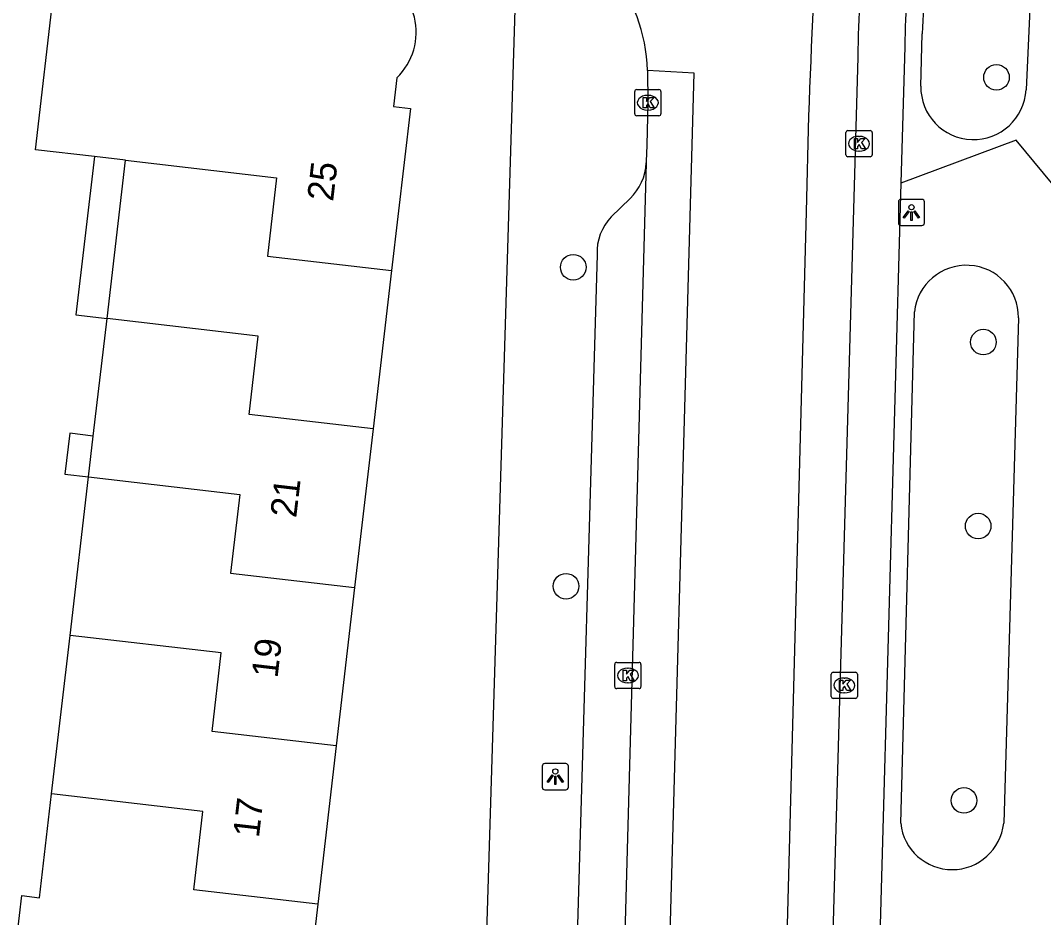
# Model space of a CAD drawing. Extents: x 162082 to 163393, y 388091 to 388632.
# Drawn here: x 162880.67 to 162919.73, y 388158.33 to 388192.57 of the extents above; entities that cross this region are included whole.
import ezdxf

# ---------------------------------------------------------------- set-up
doc = ezdxf.new("R2010")
doc.units = 0
for name, color, linetype in [('IMGEO_Boom', 7, 'Continuous'), ('IMGEO_Kolk', 7, 'Continuous'), ('IMGEO_Lichtpunt', 7, 'Continuous'), ('IMGEO_Pand', 7, 'Continuous'), ('IMGEO_Pand_nummerreeks', 7, 'Continuous'), ('IMGEO_Pand_overbouw', 7, 'Continuous'), ('IMGEO_Rijbaan_lokaal_gesloten', 7, 'Continuous'), ('IMGEO_Voetpad_open', 7, 'Continuous')]:
    doc.layers.add(name, color=color, linetype=linetype)

msp = doc.modelspace()

# ---------------------------------------------------------------- linework, layer by layer
at = {"layer": 'IMGEO_Boom'}
for centre in [(162917.93, 388190.397), (162901.772, 388183.148), (162917.431, 388180.294), (162917.231, 388173.271), (162901.498, 388170.974), (162916.689, 388162.799)]:
    msp.add_circle(centre, 0.489, dxfattribs=at)
at = {"layer": 'IMGEO_Kolk'}
for p, q in [((162904.119, 388189.004), (162904.119, 388189.856)), ((162904.194, 388189.93), (162905.046, 388189.93)), ((162905.12, 388189.856), (162905.12, 388189.004)), ((162904.607, 388189.71), (162904.632, 388189.71)), ((162904.63, 388189.15), (162904.605, 388189.15)), ((162905.046, 388188.93), (162904.194, 388188.93)), ((162912.183, 388187.44), (162912.183, 388188.292)), ((162912.258, 388188.366), (162913.11, 388188.366)), ((162913.184, 388188.292), (162913.184, 388187.44)), ((162912.671, 388188.146), (162912.696, 388188.146)), ((162912.694, 388187.586), (162912.669, 388187.586)), ((162913.11, 388187.366), (162912.258, 388187.366)), ((162903.356, 388167.141), (162903.356, 388167.993)), ((162903.431, 388168.067), (162904.283, 388168.067)), ((162904.357, 388167.993), (162904.357, 388167.141)), ((162903.844, 388167.847), (162903.869, 388167.847)), ((162911.622, 388166.765), (162911.622, 388167.617)), ((162911.697, 388167.691), (162912.549, 388167.691)), ((162912.623, 388167.617), (162912.623, 388166.765)), ((162903.867, 388167.287), (162903.842, 388167.287)), ((162912.11, 388167.471), (162912.135, 388167.471)), ((162904.283, 388167.067), (162903.431, 388167.067)), ((162912.133, 388166.911), (162912.108, 388166.911)), ((162912.549, 388166.691), (162911.697, 388166.691))]:
    msp.add_line(p, q, dxfattribs=at)
for points in [[(162904.119, 388189.004), (162904.119, 388189.856)], [(162904.194, 388189.93), (162905.046, 388189.93)], [(162905.12, 388189.856), (162905.12, 388189.004)], [(162904.44, 388189.63), (162904.563, 388189.63), (162904.563, 388189.479), (162904.693, 388189.63), (162904.857, 388189.63), (162904.711, 388189.479), (162904.864, 388189.23), (162904.712, 388189.23), (162904.627, 388189.394), (162904.563, 388189.327), (162904.563, 388189.23), (162904.44, 388189.23), (162904.44, 388189.63)], [(162905.046, 388188.93), (162904.194, 388188.93)], [(162912.183, 388187.44), (162912.183, 388188.292)], [(162912.258, 388188.366), (162913.11, 388188.366)], [(162913.184, 388188.292), (162913.184, 388187.44)], [(162912.504, 388188.066), (162912.627, 388188.066), (162912.627, 388187.915), (162912.757, 388188.066), (162912.921, 388188.066), (162912.775, 388187.915), (162912.928, 388187.666), (162912.776, 388187.666), (162912.691, 388187.83), (162912.627, 388187.763), (162912.627, 388187.666), (162912.504, 388187.666), (162912.504, 388188.066)], [(162913.11, 388187.366), (162912.258, 388187.366)], [(162903.356, 388167.141), (162903.356, 388167.993)], [(162903.431, 388168.067), (162904.283, 388168.067)], [(162904.357, 388167.993), (162904.357, 388167.141)], [(162903.677, 388167.767), (162903.8, 388167.767), (162903.8, 388167.616), (162903.93, 388167.767), (162904.094, 388167.767), (162903.948, 388167.616), (162904.101, 388167.367), (162903.949, 388167.367), (162903.864, 388167.531), (162903.8, 388167.464), (162903.8, 388167.367), (162903.677, 388167.367), (162903.677, 388167.767)], [(162911.622, 388166.765), (162911.622, 388167.617)], [(162911.697, 388167.691), (162912.549, 388167.691)], [(162912.623, 388167.617), (162912.623, 388166.765)], [(162911.943, 388167.391), (162912.066, 388167.391), (162912.066, 388167.24), (162912.196, 388167.391), (162912.36, 388167.391), (162912.214, 388167.24), (162912.367, 388166.991), (162912.215, 388166.991), (162912.13, 388167.155), (162912.066, 388167.088), (162912.066, 388166.991), (162911.943, 388166.991), (162911.943, 388167.391)], [(162904.283, 388167.067), (162903.431, 388167.067)], [(162912.549, 388166.691), (162911.697, 388166.691)]]:
    msp.add_lwpolyline(points, dxfattribs=at)
for centre, start, end in [((162904.196, 388189.854), 91.552, 178.448), ((162904.196, 388189.854), 91.552, 178.448), ((162905.044, 388189.854), 1.552, 88.448), ((162905.044, 388189.854), 1.552, 88.448), ((162904.196, 388189.006), 181.552, 268.448), ((162904.196, 388189.006), 181.552, 268.448), ((162905.044, 388189.006), 271.552, 358.448), ((162905.044, 388189.006), 271.552, 358.448), ((162912.26, 388188.29), 91.552, 178.448), ((162912.26, 388188.29), 91.552, 178.448), ((162913.108, 388188.29), 1.552, 88.448), ((162913.108, 388188.29), 1.552, 88.448), ((162912.26, 388187.442), 181.552, 268.448), ((162912.26, 388187.442), 181.552, 268.448), ((162913.108, 388187.442), 271.552, 358.448), ((162913.108, 388187.442), 271.552, 358.448), ((162903.433, 388167.991), 91.552, 178.448), ((162903.433, 388167.991), 91.552, 178.448), ((162904.281, 388167.991), 1.552, 88.448), ((162904.281, 388167.991), 1.552, 88.448), ((162911.699, 388167.615), 91.552, 178.448), ((162911.699, 388167.615), 91.552, 178.448), ((162912.547, 388167.615), 1.552, 88.448), ((162912.547, 388167.615), 1.552, 88.448), ((162903.433, 388167.143), 181.552, 268.448), ((162903.433, 388167.143), 181.552, 268.448), ((162904.281, 388167.143), 271.552, 358.448), ((162904.281, 388167.143), 271.552, 358.448), ((162911.699, 388166.767), 181.552, 268.448), ((162911.699, 388166.767), 181.552, 268.448), ((162912.547, 388166.767), 271.552, 358.448), ((162912.547, 388166.767), 271.552, 358.448)]:
    msp.add_arc(centre, 0.0765, start, end, dxfattribs=at)
for centre, major_axis, ratio, start_param, end_param in [((162904.606, 388189.43), (-0.387, 0.002), 0.722429, 4.712389, 7.853982), ((162904.631, 388189.43), (-0.39, 0.002), 0.717154, 1.570796, 4.712389), ((162912.67, 388187.866), (-0.387, 0.002), 0.722429, 4.712389, 7.853982), ((162912.695, 388187.866), (-0.39, 0.002), 0.717154, 1.570796, 4.712389), ((162903.843, 388167.567), (-0.387, 0.002), 0.722429, 4.712389, 7.853982), ((162903.868, 388167.567), (-0.39, 0.002), 0.717154, 1.570796, 4.712389), ((162912.109, 388167.191), (-0.387, 0.002), 0.722429, 4.712389, 7.853982), ((162912.134, 388167.191), (-0.39, 0.002), 0.717154, 1.570796, 4.712389)]:
    msp.add_ellipse(centre, major_axis=major_axis, ratio=ratio, start_param=start_param, end_param=end_param, dxfattribs=at)
at = {"layer": 'IMGEO_Lichtpunt'}
for p, q in [((162914.184, 388185.644), (162914.184, 388184.837)), ((162914.184, 388185.644), (162914.184, 388184.837)), ((162915.086, 388185.739), (162914.278, 388185.739)), ((162915.086, 388185.739), (162914.278, 388185.739)), ((162915.18, 388184.837), (162915.18, 388185.644)), ((162915.18, 388184.837), (162915.18, 388185.644)), ((162914.278, 388184.743), (162915.086, 388184.743)), ((162914.278, 388184.743), (162915.086, 388184.743)), ((162900.59, 388164.108), (162900.59, 388163.301)), ((162900.59, 388164.108), (162900.59, 388163.301)), ((162901.492, 388164.203), (162900.684, 388164.203)), ((162901.492, 388164.203), (162900.684, 388164.203)), ((162901.586, 388163.301), (162901.586, 388164.108)), ((162901.586, 388163.301), (162901.586, 388164.108)), ((162900.684, 388163.207), (162901.492, 388163.207)), ((162900.684, 388163.207), (162901.492, 388163.207))]:
    msp.add_line(p, q, dxfattribs=at)
for points in [[(162914.558, 388185.308), (162914.597, 388185.28), (162914.409, 388185.018), (162914.371, 388185.045), (162914.558, 388185.308)], [(162914.66, 388185.26), (162914.707, 388185.26), (162914.707, 388184.938), (162914.66, 388184.938), (162914.66, 388185.26)], [(162914.77, 388185.28), (162914.808, 388185.307), (162914.995, 388185.045), (162914.956, 388185.017), (162914.77, 388185.28)], [(162900.964, 388163.772), (162901.003, 388163.744), (162900.815, 388163.482), (162900.777, 388163.509), (162900.964, 388163.772)], [(162901.066, 388163.724), (162901.113, 388163.724), (162901.113, 388163.402), (162901.066, 388163.402), (162901.066, 388163.724)], [(162901.176, 388163.744), (162901.214, 388163.771), (162901.401, 388163.509), (162901.362, 388163.481), (162901.176, 388163.744)]]:
    msp.add_lwpolyline(points, dxfattribs=at)
for centre in [(162914.683, 388185.442), (162901.089, 388163.906)]:
    msp.add_circle(centre, 0.0994, dxfattribs=at)
for centre, start, end in [((162914.278, 388185.644), 90, 180), ((162914.278, 388185.644), 90, 180), ((162915.086, 388185.644), 0, 90), ((162915.086, 388185.644), 0, 90), ((162914.278, 388184.837), 180, 270), ((162914.278, 388184.837), 180, 270), ((162915.086, 388184.837), 270, 0), ((162915.086, 388184.837), 270, 360), ((162900.684, 388164.108), 90, 180), ((162900.684, 388164.108), 90, 180), ((162901.492, 388164.108), 0, 90), ((162901.492, 388164.108), 0, 90), ((162900.684, 388163.301), 180, 270), ((162900.684, 388163.301), 180, 270), ((162901.492, 388163.301), 270, 0), ((162901.492, 388163.301), 270, 360)]:
    msp.add_arc(centre, 0.0946, start, end, dxfattribs=at)
at = {"layer": 'IMGEO_Pand'}
for points in [[(162884.679, 388187.235), (162883.492, 388187.373), (162881.238, 388187.636), (162881.945, 388193.694), (162884.199, 388193.431), (162885.385, 388193.293), (162886.032, 388193.224), (162886.047, 388193.354), (162886.274, 388195.302)], [(162895.04, 388190.384), (162894.913, 388189.289), (162895.557, 388189.214), (162894.835, 388183.019)], [(162883.973, 388181.189), (162884.679, 388187.235)], [(162884.679, 388187.235), (162890.448, 388186.562), (162890.099, 388183.567), (162894.835, 388183.019)], [(162894.835, 388183.019), (162894.13, 388176.976)], [(162883.268, 388175.144), (162883.45, 388176.705), (162883.973, 388181.189)], [(162894.13, 388176.976), (162889.395, 388177.523), (162889.743, 388180.516), (162883.973, 388181.189)], [(162894.13, 388176.976), (162893.425, 388170.931)], [(162882.563, 388169.099), (162883.268, 388175.144)], [(162883.268, 388175.144), (162889.039, 388174.471), (162888.69, 388171.479), (162893.425, 388170.931)], [(162893.425, 388170.931), (162892.72, 388164.887)], [(162881.858, 388163.054), (162882.563, 388169.099)], [(162892.72, 388164.887), (162887.986, 388165.434), (162888.335, 388168.426), (162882.563, 388169.099)], [(162892.72, 388164.887), (162892.016, 388158.844)], [(162886.538, 388153.202), (162886.886, 388156.19), (162881.136, 388156.86), (162881.218, 388157.567), (162880.543, 388157.646), (162880.72, 388159.165), (162881.396, 388159.086), (162881.858, 388163.054)], [(162892.016, 388158.844), (162887.282, 388159.391), (162887.631, 388162.381), (162881.858, 388163.054)], [(162892.016, 388158.844), (162891.305, 388152.751)]]:
    msp.add_lwpolyline(points, dxfattribs=at)
msp.add_arc((162893.379, 388192.114), 2.398, 313.8375, 74.1281, dxfattribs=at)
at = {"layer": 'IMGEO_Pand_overbouw'}
for points in [[(162884.679, 388187.235), (162883.492, 388187.373), (162882.787, 388181.327), (162883.973, 388181.189)], [(162883.45, 388176.705), (162882.548, 388176.811), (162882.367, 388175.257), (162883.268, 388175.144)]]:
    msp.add_lwpolyline(points, close=True, dxfattribs=at)
at = {"layer": 'IMGEO_Rijbaan_lokaal_gesloten'}
for points in [[(162912.631, 388191.173), (162910.923, 388130.952)], [(162904.079, 388107.506), (162906.386, 388190.56), (162904.604, 388190.663)], [(162904.604, 388190.663), (162904.62, 388189.43), (162904.578, 388187.81), (162904.562, 388187.183), (162904.56, 388187.129)], [(162904.56, 388187.129), (162903.584, 388152.171)], [(162910.663, 388185.26), (162908.585, 388107.428)]]:
    msp.add_lwpolyline(points, dxfattribs=at)
for centre, radius, start, end in [((162898.311, 388190.509), 6.295, 1.4052, 76.5995), ((162980.265, 388189.981), 67.644, 175.1072, 178.99072), ((163166.35, 388180.411), 255.733, 177.03224, 178.91347)]:
    msp.add_arc(centre, radius, start, end, dxfattribs=at)
at = {"layer": 'IMGEO_Voetpad_open'}
for points in [[(162898.299, 388151.949), (162899.578, 388193.832)], [(162919.218, 388193.291), (162919.061, 388189.927)], [(162915.041, 388190.063), (162915.096, 388192.057)], [(162914.425, 388191.58), (162914.279, 388186.363)], [(162921.806, 388184.224), (162918.683, 388187.995), (162914.279, 388186.363)], [(162914.279, 388186.363), (162912.825, 388134.303)], [(162903.945, 388185.769), (162903.226, 388185.072)], [(162902.681, 388183.637), (162901.864, 388155.441)], [(162914.274, 388161.925), (162914.797, 388181.442)], [(162918.772, 388181.219), (162918.207, 388161.93)]]:
    msp.add_lwpolyline(points, dxfattribs=at)
for centre, radius, start, end in [((162975.202, 388189.993), 60.142, 174.20419, 178.03298), ((162972.396, 388190.255), 57.986, 174.70824, 178.69075), ((162917.052, 388190.032), 2.011, 179.109, 357.0158), ((162902.48, 388187.251), 2.084, 314.6826, 356.6519), ((162904.602, 388183.728), 1.923, 135.6803, 182.727), ((162916.779, 388181.232), 1.993, 359.6377, 173.9403), ((162916.24, 388162.137), 1.978, 186.1395, 354.0062)]:
    msp.add_arc(centre, radius, start, end, dxfattribs=at)

# ---------------------------------------------------------------- texts
at = {"layer": 'IMGEO_Pand_nummerreeks'}
for s, rotation, p in [('25', 83.3482, (162892.603, 388185.638)), ('21', 83.3482, (162891.195, 388173.561)), ('19', 83.3487, (162890.481, 388167.446)), ('17', 83.3487, (162889.771, 388161.351))]:
    msp.add_text(s, height=1, rotation=rotation, dxfattribs=at).set_placement(p)

doc.saveas('drawing.dxf')
